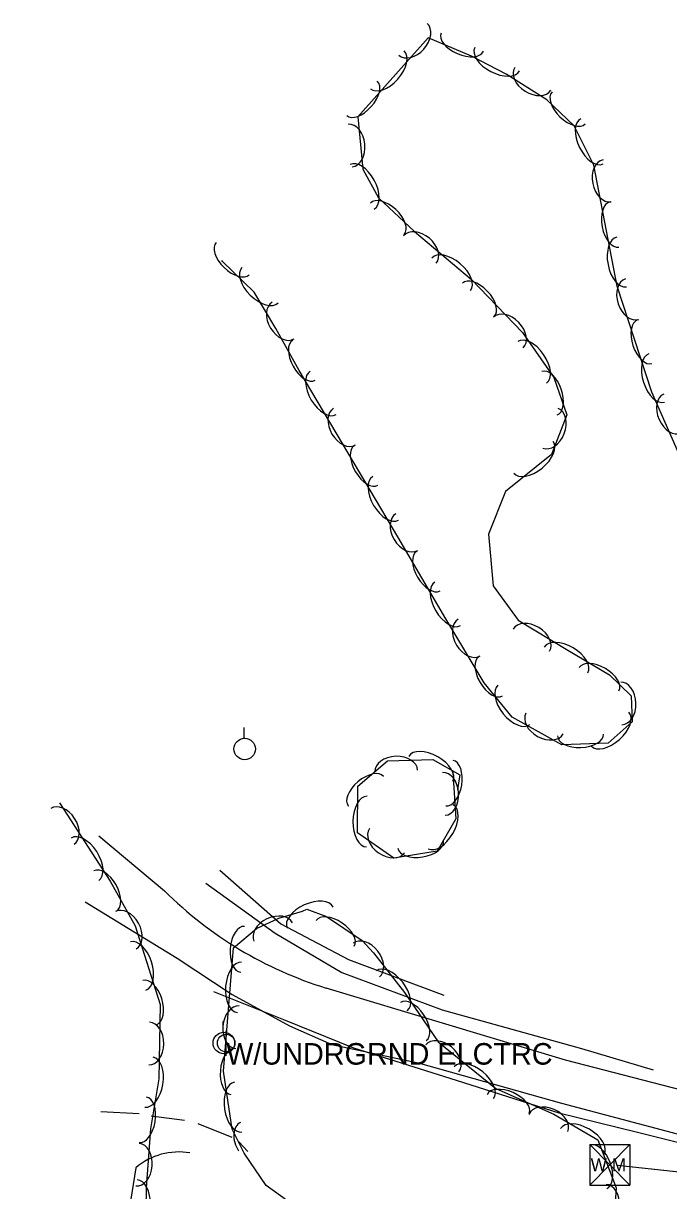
# Model space of a CAD drawing. Extents: x 954793 to 988390, y 1867850 to 1924428.
# Drawn here: x 961078.3 to 961228.1, y 1906610.1 to 1906881.1 of the extents above; entities that cross this region are included whole.
import ezdxf

# ---------------------------------------------------------------- set-up
doc = ezdxf.new("R2010")
doc.units = 0
for name, color, linetype in [('S_DITCHLINE', 7, 'Continuous'), ('S_DRIVEWAY', 7, 'Continuous'), ('S_FENCE', 7, 'Continuous'), ('S_TREE', 7, 'Continuous'), ('S_UTILITY_POLE', 7, 'Continuous'), ('S_UTILITY_POLE_ANNOT', 7, 'Continuous'), ('S_UTL_PT_SYM', 7, 'Continuous'), ('S_WATER_UTILITIES', 7, 'Continuous')]:
    doc.layers.add(name, color=color, linetype=linetype)

msp = doc.modelspace()

# ---------------------------------------------------------------- linework, layer by layer
at = {"layer": 'S_DITCHLINE'}
for points in [[(961123.91, 1906684.52), (961138.09, 1906672.05), (961153.78, 1906663.73), (961175.89, 1906655.47)], [(961120.67, 1906681.48), (961136.71, 1906669.91), (961152.25, 1906660.71), (961175.47, 1906652.11), (961191.66, 1906647.6), (961207.85, 1906643.09), (961224.46, 1906638.18)], [(961122.41, 1906656.35), (961138.69, 1906649.81), (961154.96, 1906643.28), (961178.77, 1906635.73), (961202.58, 1906628.18), (961220.86, 1906623.65), (961239.14, 1906619.13)]]:
    msp.add_lwpolyline(points, dxfattribs=at)
at = {"layer": 'S_DRIVEWAY'}
for points in [[(961111.09, 1906679.66), (961095.84, 1906692.42)], [(961092.65, 1906677.15), (961114.01, 1906664.04), (961126.75, 1906655.67), (961140.1, 1906648.36), (961149.88, 1906644.05), (961169.95, 1906639.81), (961203.18, 1906630.39), (961241.41, 1906620.31), (961261.98, 1906612.85)], [(961261.73, 1906626.99), (961235.58, 1906632.27), (961204.15, 1906640.42), (961148.57, 1906657.12)], [(961104.38, 1906615.41), (961100.19, 1906589.21)]]:
    msp.add_lwpolyline(points, dxfattribs=at)
for centre, major_axis, ratio, start_param, end_param in [((961175.57, 1906744.56), (-33.91, -84.99), 0.997864, 5.879851, 6.363523), ((961114.31, 1906603.82), (14.98, 2.91), 0.999891, 1.204076, 2.087256)]:
    msp.add_ellipse(centre, major_axis=major_axis, ratio=ratio, start_param=start_param, end_param=end_param, dxfattribs=at)
at = {"layer": 'S_FENCE'}
for points in [[(961096.27, 1906628.44), (961105.17, 1906628.03)], [(961107.95, 1906627.47), (961115.68, 1906626.44)], [(961118.82, 1906625.71), (961126.67, 1906622.54)], [(961128.3, 1906621.4), (961130.43, 1906619.23)]]:
    msp.add_lwpolyline(points, dxfattribs=at)
at = {"layer": 'S_TREE'}
for points in [[(961232.03, 1906777.52), (961224.14, 1906795.49), (961216.1, 1906820.03), (961210.68, 1906848.12), (961206.12, 1906857.28), (961199.82, 1906863.35), (961190.39, 1906869.25), (961182.34, 1906873.46), (961172.27, 1906877.75), (961155.93, 1906859.4), (961157.1, 1906847.24), (961160.73, 1906840.54), (961169.12, 1906832.73), (961182.32, 1906821.61), (961194.15, 1906809.31), (961201.4, 1906798.88), (961204.41, 1906790.19), (961200.87, 1906781), (961190.22, 1906772.42), (961186.26, 1906762.48), (961187.36, 1906750.53), (961193.11, 1906742.56), (961204.65, 1906735.55), (961214.36, 1906729.86), (961219.41, 1906724.98), (961219.6, 1906718.96), (961214.02, 1906713.97), (961203.32, 1906713.57), (961191.77, 1906719.98), (961185.26, 1906727.96), (961176.39, 1906742.84), (961165.2, 1906761.84), (961152.41, 1906783.54), (961142.35, 1906800.46), (961136.91, 1906810.26), (961131.84, 1906818.65), (961124.52, 1906825.82), (961124.35, 1906825.99)], [(961177.99, 1906707.28), (961178.65, 1906696.4), (961174.36, 1906688.91), (961164.32, 1906687.27), (961155.86, 1906693.18), (961155.96, 1906704.02), (961162.83, 1906709.85), (961173.34, 1906710.21), (961179.64, 1906706.65), (961179.09, 1906703.22)], [(961086.65, 1906700.11), (961098.43, 1906681.96), (961104.22, 1906671.58), (961110.03, 1906653.31), (961109.75, 1906636.03), (961107.82, 1906624.43), (961106.78, 1906610.79), (961106.49, 1906590.76), (961105.83, 1906572.71), (961105.65, 1906553.79), (961108.67, 1906534.3), (961109.44, 1906516.34), (961109.75, 1906497.91), (961109.55, 1906479.28), (961109.1, 1906466.95), (961105.91, 1906459.63), (961096.97, 1906455.54), (961089.05, 1906455.34), (961081.27, 1906455.22), (961075.79, 1906468.62)], [(961142.73, 1906605.51), (961134.65, 1906611.32), (961129.58, 1906618.83), (961126.79, 1906624.38), (961124.78, 1906637.86), (961127.08, 1906666.49), (961132.42, 1906670.92), (961137.59, 1906673.37), (961143.06, 1906675.01), (961144.08, 1906675.48), (961148.65, 1906673.73), (961156.9, 1906668.21), (961159.6, 1906665.29), (961166.79, 1906656.12), (961174.56, 1906644.68), (961187.93, 1906633.81), (961201.43, 1906627.86), (961211.67, 1906621.91), (961215.93, 1906610.72), (961215.15, 1906598.9)]]:
    msp.add_lwpolyline(points, dxfattribs=at)
for centre, major_axis, ratio, end_param in [((961168.74, 1906877.37), (3.29, 3.7), 0.685311, 6.283185), ((961180.16, 1906876.7), (4.92, -2.1), 0.540699, 6.283185), ((961162.78, 1906870.28), (3.9, 4.38), 0.55008, 6.283185), ((961188.28, 1906872.75), (5.2, -2.72), 0.55008, 6.283185), ((961196.54, 1906868.21), (4.2, -2.63), 0.685311, 6.283185), ((961156.89, 1906863.66), (3.55, 3.99), 0.540699, 6.283185), ((961204.86, 1906861.44), (3.85, -3.71), 0.540699, 6.283185), ((961154.18, 1906852.72), (-0.47, 4.93), 0.685311, 6.283185), ((961210.28, 1906853.69), (2.62, -5.25), 0.55008, 6.283185), ((961156.92, 1906843.13), (-2.8, 5.16), 0.55008, 6.283185), ((961213.8, 1906844.55), (0.94, -4.87), 0.685311, 6.283185), ((961162.78, 1906835.73), (-3.91, 3.64), 0.540699, 6.283185), ((961215.49, 1906834.38), (1.01, -5.25), 0.540699, 6.283185), ((961170.35, 1906828.58), (-3.79, 3.19), 0.685311, 6.283185), ((961217.17, 1906825.68), (1.11, -5.76), 0.55008, 6.283185), ((961126.89, 1906826.47), (3.82, -3.74), 0.540699, 6.283185), ((961177.61, 1906822.81), (-4.49, 3.78), 0.55008, 6.283185), ((961133.22, 1906820.27), (4.19, -4.11), 0.55008, 6.283185), ((961183.9, 1906816.91), (-3.71, 3.85), 0.540699, 6.283185), ((961219.58, 1906817.05), (1.54, -4.71), 0.685311, 6.283185), ((961138.59, 1906812.08), (2.56, -4.24), 0.685311, 6.283185), ((961190.86, 1906809.3), (-3.43, 3.57), 0.685311, 6.283185), ((961222.54, 1906807.18), (1.67, -5.08), 0.540699, 6.283185), ((961143.43, 1906802.88), (2.6, -4.67), 0.540699, 6.283185), ((961196.39, 1906802.37), (-3.35, 4.82), 0.55008, 6.283185), ((961225.31, 1906798.75), (1.83, -5.58), 0.55008, 6.283185), ((961200.42, 1906795.21), (-1.75, 5.05), 0.540699, 6.283185), ((961147.89, 1906795.29), (3, -5.05), 0.55008, 6.283185), ((961228.95, 1906790.48), (1.99, -4.54), 0.685311, 6.283185), ((961152.85, 1906787.46), (2.53, -4.26), 0.685311, 6.283185), ((961200.66, 1906787.08), (1.79, 4.62), 0.685311, 6.283185), ((961157.87, 1906778.45), (2.72, -4.61), 0.540699, 6.283185), ((961196.68, 1906780.36), (4.57, 3.68), 0.55008, 6.283185), ((961162.37, 1906770.82), (2.98, -5.06), 0.55008, 6.283185), ((961167.3, 1906762.97), (2.52, -4.27), 0.685311, 6.283185), ((961172.3, 1906753.96), (2.71, -4.61), 0.540699, 6.283185), ((961176.81, 1906746.32), (2.98, -5.06), 0.55008, 6.283185), ((961181.75, 1906738.5), (2.54, -4.26), 0.685311, 6.283185), ((961196.2, 1906737.89), (-4.24, 2.57), 0.685311, 6.283185), ((961204.28, 1906733.31), (-5.06, 2.97), 0.55008, 6.283185), ((961186.8, 1906729.52), (2.74, -4.59), 0.540699, 6.283185), ((961211.93, 1906728.82), (-4.61, 2.7), 0.540699, 6.283185), ((961217.09, 1906723.2), (-0.15, 4.95), 0.685311, 6.283185), ((961192.17, 1906722.86), (3.71, -4.55), 0.55008, 6.283185), ((961199.29, 1906718.53), (4.33, -2.41), 0.685311, 6.283185), ((961214.5, 1906717.24), (4.37, 3.91), 0.55008, 6.283185), ((961207.61, 1906715.85), (5.34, 0.2), 0.540699, 6.283185), ((961172.88, 1906708.03), (-5.11, 2.89), 0.55008, 6.283185), ((961164.85, 1906707.54), (-4.95, -0.17), 0.685311, 6.283185), ((961177.18, 1906704.71), (0.86, 5.28), 0.540699, 6.283185), ((961157.82, 1906702.82), (-4.08, -3.46), 0.540699, 6.283185), ((961175.92, 1906702.19), (-0.3, 4.95), 0.685311, 6.283185), ((961158.01, 1906695.77), (-0.06, -5.87), 0.55008, 6.283185), ((961087.35, 1906694.66), (-2.7, 4.16), 0.685311, 6.283185), ((961175.17, 1906694.58), (2.92, 5.09), 0.55008, 6.283185), ((961092.61, 1906687.04), (-3.2, 4.92), 0.55008, 6.283185), ((961162.67, 1906691.33), (4.06, -2.84), 0.685311, 6.283185), ((961170.52, 1906690.43), (5.28, 0.86), 0.540699, 6.283185), ((961097.28, 1906679.67), (-2.6, 4.67), 0.540699, 6.283185), ((961144.84, 1906673.5), (-5.34, -2.44), 0.55008, 6.283185), ((961102.07, 1906670.54), (-2.41, 4.33), 0.685311, 6.283185), ((961136.3, 1906670.12), (-4.48, -2.12), 0.685311, 6.283185), ((961150.67, 1906669.83), (-4.44, 2.97), 0.540699, 6.283185), ((961129.17, 1906666.12), (-0.43, -5.33), 0.540699, 6.283185), ((961104.96, 1906662.25), (-1.78, 5.59), 0.55008, 6.283185), ((961157.88, 1906663.63), (-3.06, 3.9), 0.685311, 6.283185), ((961128.47, 1906657.28), (-0.47, -5.85), 0.55008, 6.283185), ((961163.8, 1906656.5), (-3.62, 4.62), 0.55008, 6.283185), ((961107.65, 1906653.8), (-1.62, 5.09), 0.540699, 6.283185), ((961168.81, 1906649.37), (-3, 4.42), 0.540699, 6.283185), ((961127.99, 1906648.03), (-0.4, -4.94), 0.685311, 6.283185), ((961107.5, 1906644.23), (0.08, 4.95), 0.685311, 6.283185), ((961175.53, 1906640.82), (-3.85, 3.13), 0.685311, 6.283185), ((961107.48, 1906635.3), (0.96, 5.79), 0.55008, 6.283185), ((961126.9, 1906637.78), (-0.43, -5.33), 0.540699, 6.283185), ((961182.88, 1906635.18), (-4.55, 3.7), 0.55008, 6.283185), ((961128.17, 1906629.5), (0.87, -5.8), 0.55008, 6.283185), ((961190.81, 1906630.22), (-4.89, 2.16), 0.540699, 6.283185), ((961106.02, 1906626.55), (0.88, 5.27), 0.540699, 6.283185), ((961200.14, 1906625.82), (-4.53, 2), 0.685311, 6.283185), ((961130.9, 1906621.51), (2.22, -4.43), 0.685311, 4.868429), ((961208.06, 1906621.55), (-5.07, 2.95), 0.55008, 6.283185), ((961104.8, 1906616.13), (0.38, 4.94), 0.685311, 6.283185), ((961211.79, 1906615.62), (-1.9, 5), 0.540699, 6.283185), ((961104.6, 1906606.74), (0.08, 5.87), 0.55008, 6.283185), ((961213.27, 1906606.63), (0.33, 4.94), 0.685311, 6.283185)]:
    msp.add_ellipse(centre, major_axis=major_axis, ratio=ratio, start_param=3.141593, end_param=end_param, dxfattribs=at)
at = {"layer": 'S_UTILITY_POLE'}
for p, q in [((961129.53, 1906715.15), (961129.53, 1906717.63)), ((961124.69, 1906646.89), (961124.69, 1906649.37)), ((961125.37, 1906641.43), (961125.37, 1906647.22))]:
    msp.add_line(p, q, dxfattribs=at)
for centre, radius in [((961129.67, 1906712.63), 2.5), ((961124.83, 1906644.37), 2.5), ((961125.37, 1906644.36), 2.05)]:
    msp.add_circle(centre, radius, dxfattribs=at)
at = {"layer": 'S_UTL_PT_SYM'}
msp.add_lwpolyline([(961216.15, 1906615.94), (961216.15, 1906615.89), (961216.15, 1906615.94), (961216.2, 1906615.94), (961216.15, 1906615.94), (961216.16, 1906615.99), (961216.15, 1906615.94), (961216.1, 1906615.95)], close=True, dxfattribs=at)
msp.add_lwpolyline([(961216.15, 1906615.94), (961216.15, 1906615.89), (961216.15, 1906615.94), (961216.2, 1906615.94), (961216.15, 1906615.94), (961216.16, 1906615.99), (961216.15, 1906615.94), (961216.1, 1906615.95)], close=True, dxfattribs=at)
msp.add_lwpolyline([(961216.15, 1906615.94), (961216.15, 1906615.99), (961216.15, 1906615.94), (961216.1, 1906615.94), (961216.15, 1906615.94), (961216.15, 1906615.89), (961216.15, 1906615.94), (961216.2, 1906615.94)], dxfattribs=at)
at = {"layer": 'S_WATER_UTILITIES'}
for p, q in [((961209.76, 1906620.85), (961219.1, 1906620.85)), ((961209.76, 1906620.85), (961209.76, 1906611.36)), ((961209.76, 1906620.85), (961219.1, 1906611.36)), ((961219.1, 1906620.85), (961209.76, 1906611.36)), ((961219.1, 1906620.85), (961219.1, 1906611.36)), ((961239.14, 1906613.46), (961216.15, 1906615.94)), ((961209.76, 1906611.36), (961219.1, 1906611.36))]:
    msp.add_line(p, q, dxfattribs=at)
msp.add_lwpolyline([(961239.14, 1906613.46), (961216.15, 1906615.94)], dxfattribs=at)
msp.add_lwpolyline([(961239.14, 1906613.46), (961216.15, 1906615.94)], dxfattribs=at)

# ---------------------------------------------------------------- texts
at = {"layer": 'S_UTILITY_POLE_ANNOT'}
msp.add_text('W/UNDRGRND ELCTRC', height=5, dxfattribs=at).set_placement((961125.37, 1906639.36))
at = {"layer": 'S_WATER_UTILITIES'}
msp.add_text('W M', height=3, rotation=360, dxfattribs=at).set_placement((961209.97, 1906614.62))

doc.saveas('drawing.dxf')
